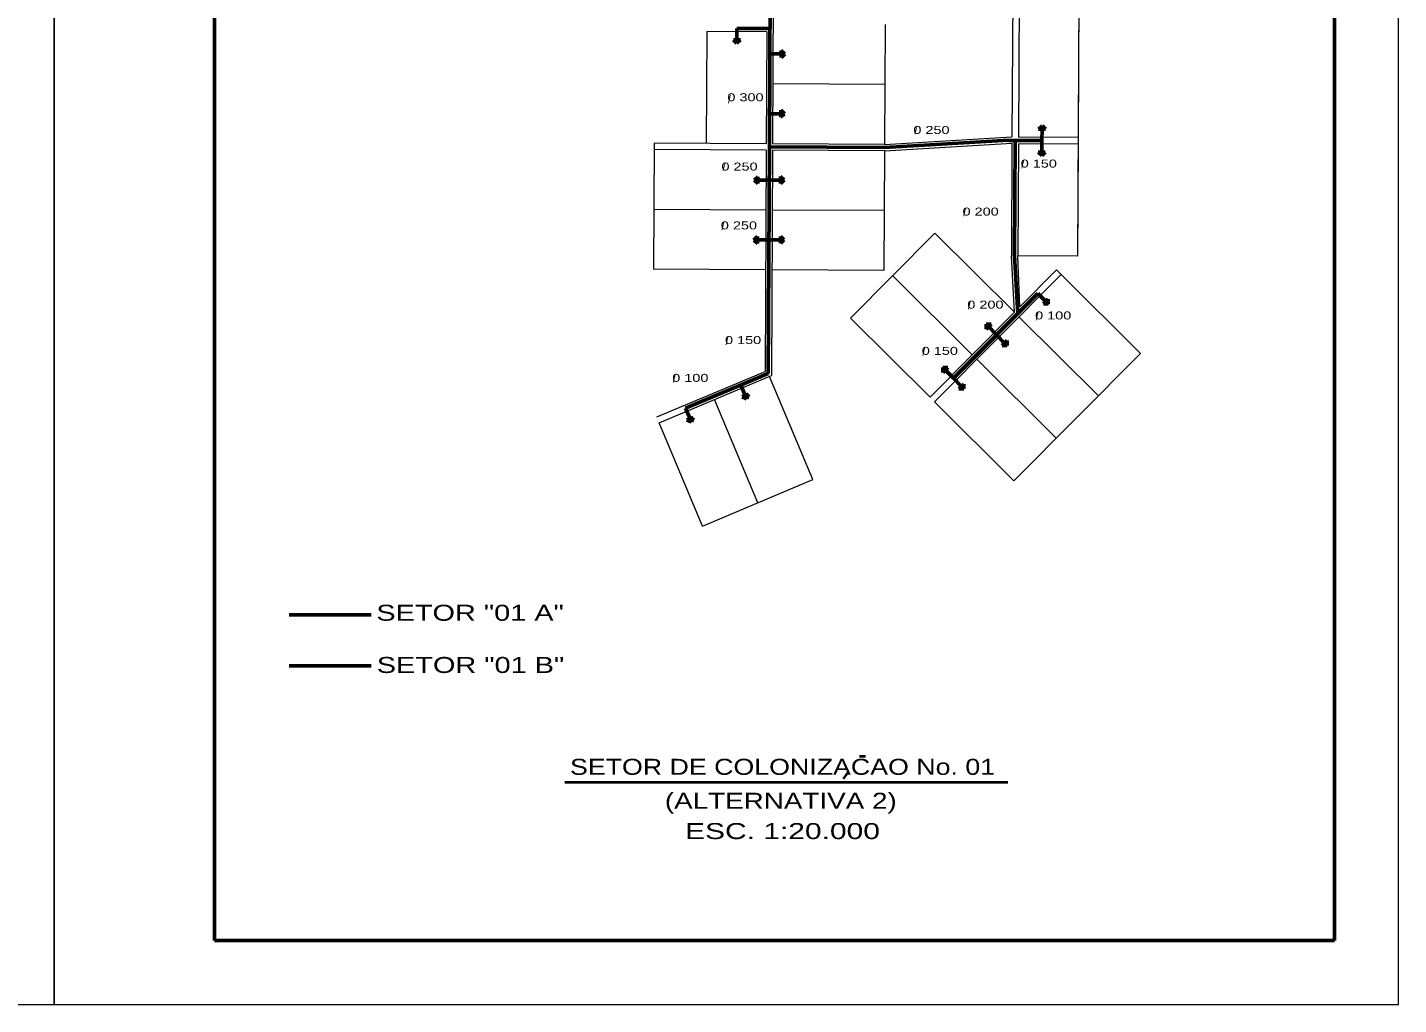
# Model space of a CAD drawing. Extents: x 312964 to 351929, y 9004151 to 9034973.
# Drawn here: x 347467 to 351751, y 9013061 to 9016114 of the extents above; entities that cross this region are included whole.
import ezdxf
from ezdxf.enums import TextEntityAlignment as Align

# ---------------------------------------------------------------- set-up
doc = ezdxf.new("R2010")
doc.units = 0
doc.header["$LTSCALE"] = 10
doc.layers.add('1', color=7, linetype='Continuous', lineweight=13)
doc.layers.add('2', color=7, linetype='Continuous', lineweight=53)

msp = doc.modelspace()

# ---------------------------------------------------------------- linework, layer by layer
at = {"layer": '1', "lineweight": 53}
for p, q in [((348050.92, 9018801.07), (348050.92, 9013261.07)), ((351550.92, 9013261.07), (351550.92, 9018801.07)), ((349786.74, 9016110.55), (349683.24, 9016111.06)), ((349683.29, 9016075.21), (349683.24, 9016111.06)), ((349672.77, 9016075.2), (349694.33, 9016075.23)), ((349683.56, 9016064.43), (349672.77, 9016075.2)), ((349683.56, 9016064.43), (349694.33, 9016075.23)), ((349822.2, 9016031.1), (349786.35, 9016031.05)), ((349822.21, 9016020.58), (349822.19, 9016042.14)), ((349832.98, 9016031.37), (349822.19, 9016042.14)), ((349832.98, 9016031.37), (349822.21, 9016020.58)), ((349821.3, 9015833.58), (349821.27, 9015855.14)), ((349832.06, 9015844.38), (349821.27, 9015855.14)), ((349821.28, 9015844.1), (349785.44, 9015844.06)), ((349832.06, 9015844.38), (349821.3, 9015833.58)), ((350637.1, 9015807.01), (350626.13, 9015796.42)), ((350637.1, 9015807.01), (350647.69, 9015796.04)), ((350647.69, 9015796.04), (350626.13, 9015796.42)), ((350637.17, 9015796.23), (350636.54, 9015760.38)), ((350145.56, 9015738.79), (349784.93, 9015740.56)), ((350144.92, 9015738.77), (350533.04, 9015761.5)), ((350636.54, 9015760.38), (350533.04, 9015760.89)), ((350553.04, 9015761.41), (350551.27, 9015400.8)), ((350625.38, 9015724.73), (350646.94, 9015724.34)), ((350635.97, 9015713.76), (350625.38, 9015724.73)), ((350635.9, 9015724.54), (350636.54, 9015760.38)), ((350635.97, 9015713.76), (350646.94, 9015724.34)), ((349737.79, 9015636.74), (349748.56, 9015647.53)), ((349737.79, 9015636.74), (349748.59, 9015625.97)), ((349748.56, 9015647.53), (349748.59, 9015625.97)), ((349748.57, 9015637.01), (349784.42, 9015637.06)), ((349820.27, 9015637.11), (349784.42, 9015637.06)), ((349820.28, 9015626.59), (349820.25, 9015648.14)), ((349831.05, 9015637.38), (349820.25, 9015648.14)), ((349831.05, 9015637.38), (349820.28, 9015626.59)), ((349736.88, 9015449.74), (349747.64, 9015460.53)), ((349736.88, 9015449.74), (349747.67, 9015438.97)), ((349747.64, 9015460.53), (349747.67, 9015438.97)), ((349747.66, 9015450.01), (349783.5, 9015450.06)), ((349819.35, 9015450.11), (349783.5, 9015450.06)), ((349819.37, 9015439.59), (349819.34, 9015461.15)), ((349830.13, 9015450.38), (349819.34, 9015461.15)), ((349830.13, 9015450.38), (349819.37, 9015439.59)), ((350561.36, 9015220.52), (350551.27, 9015400.8)), ((350623.67, 9015283.18), (350359.94, 9015017.99)), ((350648.64, 9015257.45), (350623.67, 9015283.18)), ((350641.09, 9015250.13), (350656.56, 9015265.14)), ((350656.33, 9015249.9), (350641.09, 9015250.13)), ((350656.33, 9015249.9), (350656.56, 9015265.14)), ((350462.29, 9015187.02), (350462.06, 9015171.78)), ((350477.53, 9015186.79), (350462.06, 9015171.78)), ((350462.29, 9015187.02), (350477.53, 9015186.79)), ((350469.98, 9015179.47), (350494.95, 9015153.74)), ((350519.91, 9015128.02), (350494.95, 9015153.74)), ((350512.36, 9015120.69), (350527.84, 9015135.71)), ((350527.61, 9015120.46), (350527.84, 9015135.71)), ((350527.61, 9015120.46), (350512.36, 9015120.69)), ((350327.28, 9015051.27), (350327.06, 9015036.03)), ((350342.53, 9015051.05), (350327.06, 9015036.03)), ((350327.28, 9015051.27), (350342.53, 9015051.05)), ((350334.98, 9015043.72), (350359.94, 9015017.99)), ((349523.28, 9014924.38), (349781.46, 9015032.87)), ((349709.54, 9014963.77), (349695.61, 9014996.8)), ((350384.91, 9014992.27), (350359.94, 9015017.99)), ((350377.36, 9014984.94), (350392.83, 9014999.96)), ((350392.6, 9014984.71), (350392.83, 9014999.96)), ((349699.85, 9014959.68), (349719.71, 9014968.06)), ((349713.97, 9014953.93), (349699.85, 9014959.68)), ((349713.97, 9014953.93), (349719.71, 9014968.06)), ((350392.6, 9014984.71), (350377.36, 9014984.94)), ((349537.21, 9014891.35), (349523.28, 9014924.38)), ((349527.52, 9014887.26), (349547.38, 9014895.64)), ((349541.64, 9014881.52), (349527.52, 9014887.26)), ((349541.64, 9014881.52), (349547.38, 9014895.64)), ((348285.14, 9014278.44), (348541.08, 9014278.44)), ((348285.14, 9014119.43), (348541.08, 9014119.43)), ((348050.92, 9013261.07), (351550.92, 9013261.07))]:
    msp.add_line(p, q, dxfattribs=at)
at = {"layer": '1', "lineweight": 40}
for p, q in [((350066.77, 9013837.69), (350085.06, 9013837.69)), ((349145.51, 9013756.03), (350529.85, 9013756.03)), ((350028.79, 9013785.6), (350016.12, 9013765.89))]:
    msp.add_line(p, q, dxfattribs=at)
at = {"layer": '1'}
for points in [[(343350.92, 9019001.07), (343350.92, 9013061.07), (347550.92, 9013061.07), (347550.92, 9019001.07)], [(347550.92, 9019001.07), (347550.92, 9013061.07), (351750.92, 9013061.07), (351750.92, 9019001.07)]]:
    msp.add_lwpolyline(points, close=True, dxfattribs=at)
at = {"layer": '1', "lineweight": 53}
msp.add_lwpolyline([(349788.55, 9016479.55), (349784.93, 9015740.56), (349781.46, 9015032.87)], dxfattribs=at)
at = {"layer": '2', "lineweight": 13}
for p, q in [((349798.53, 9016474.5), (349794.98, 9015750.51)), ((350546.52, 9016470.83), (350543.09, 9015772.11)), ((350566.52, 9016470.73), (350563.09, 9015770.74)), ((350753.51, 9016469.82), (350748.27, 9015399.83)), ((350753.51, 9016469.82), (350750.08, 9015769.83)), ((350146.81, 9016122.79), (350144.97, 9015748.79)), ((349589.69, 9016101.52), (349587.98, 9015751.52)), ((349776.69, 9016100.6), (349589.69, 9016101.52)), ((349776.69, 9016100.6), (349774.98, 9015750.61)), ((350145.89, 9015935.79), (349795.89, 9015937.51)), ((350144.97, 9015748.79), (350543.09, 9015772.11)), ((350750.08, 9015769.83), (350563.09, 9015770.74)), ((349424.98, 9015752.32), (349423.05, 9015358.33)), ((349774.88, 9015730.61), (349424.88, 9015732.32)), ((349774.98, 9015750.61), (349424.98, 9015752.32)), ((349774.88, 9015730.61), (349771.49, 9015039.53)), ((349794.88, 9015730.51), (349791.43, 9015026.21)), ((350145.51, 9015728.79), (349794.88, 9015730.51)), ((350144.97, 9015748.79), (349794.98, 9015750.51)), ((350144.87, 9015728.79), (350143.04, 9015354.8)), ((350145.51, 9015728.79), (350542.99, 9015752.07)), ((350542.99, 9015752.07), (350541.27, 9015400.85)), ((350562.99, 9015750.74), (350561.27, 9015400.75)), ((350749.99, 9015749.83), (350562.99, 9015750.74)), ((350749.99, 9015749.83), (350748.27, 9015399.83)), ((349773.96, 9015543.61), (349423.97, 9015545.32)), ((350143.96, 9015541.79), (349793.96, 9015543.51)), ((350302.48, 9015470.74), (350038.75, 9015205.56)), ((350550.65, 9015223.93), (350302.48, 9015470.74)), ((350550.65, 9015223.93), (350541.27, 9015400.85)), ((350748.27, 9015399.83), (350561.27, 9015400.75)), ((350567.78, 9015241.15), (350561.27, 9015400.75)), ((349773.05, 9015356.61), (349423.05, 9015358.33)), ((350143.04, 9015354.8), (349793.05, 9015356.51)), ((350418.79, 9015091.34), (350170.62, 9015338.15)), ((350696.7, 9015342.42), (350301.1, 9014944.65)), ((350682.52, 9015356.53), (350567.78, 9015241.15)), ((350682.52, 9015356.53), (350696.7, 9015342.42)), ((350696.7, 9015342.42), (350944.86, 9015095.62)), ((350550.65, 9015223.93), (350286.92, 9014958.75)), ((350564.83, 9015209.83), (350813, 9014963.03)), ((350286.92, 9014958.75), (350038.75, 9015205.56)), ((350944.86, 9015095.62), (350549.27, 9014697.84)), ((349433.21, 9014897.37), (349771.49, 9015039.53)), ((350432.97, 9015077.24), (350681.13, 9014830.43)), ((349440.96, 9014878.94), (349791.43, 9015026.21)), ((349921.35, 9014701.16), (349785.75, 9015023.83)), ((349748.95, 9014628.72), (349613.35, 9014951.38)), ((350301.1, 9014944.65), (350549.27, 9014697.84)), ((349576.55, 9014556.27), (349440.96, 9014878.94)), ((349576.55, 9014556.27), (349921.35, 9014701.16))]:
    msp.add_line(p, q, dxfattribs=at)

# ---------------------------------------------------------------- texts
at = {"layer": '1'}
for p in [(349660.3, 9015877.37), (350243.24, 9015780.81), (349643.58, 9015666.41), (350576.79, 9015673.93), (350395.01, 9015523.89), (349639.83, 9015480.74), (350410.01, 9015233.2), (350621.76, 9015199.44), (349652.93, 9015122.54), (350267.59, 9015088.79), (349488.02, 9015004.39)]:
    msp.add_text('/', height=25, dxfattribs=at).set_placement(p, align=Align.CENTER)
for s, height, width, p in [('0 300', 25, 1.35, (349710.41, 9015883.39)), ('0 250', 25, 1.35, (350291.47, 9015781.2)), ('0 250', 25, 1.35, (349691.81, 9015666.8)), ('0 150', 25, 1.35, (350626.89, 9015676.2)), ('0 200', 25, 1.35, (350445.12, 9015526.16)), ('0 250', 25, 1.35, (349689.93, 9015483.01)), ('0 200', 25, 1.35, (350460.11, 9015235.47)), ('0 100', 25, 1.35, (350671.87, 9015201.71)), ('0 150', 25, 1.35, (349703.04, 9015124.81)), ('0 150', 25, 1.35, (350317.69, 9015091.05)), ('0 100', 25, 1.35, (349538.13, 9015006.66)), ('SETOR "01 A"', 50, 1.35, (348849.95, 9014260.26)), ('SETOR "01 B"', 50, 1.35, (348851.29, 9014097.1)), ('SETOR DE COLONIZACAO No. 01', 50, 1.25, (349826.2, 9013778.9)), ('(ALTERNATIVA 2)', 50, 1.3, (349820.76, 9013672.79)), ('ESC. 1:20.000', 50, 1.4, (349826.02, 9013578.14))]:
    msp.add_text(s, height=height, dxfattribs=dict(at, width=width)).set_placement(p, align=Align.CENTER)

doc.saveas('drawing.dxf')
